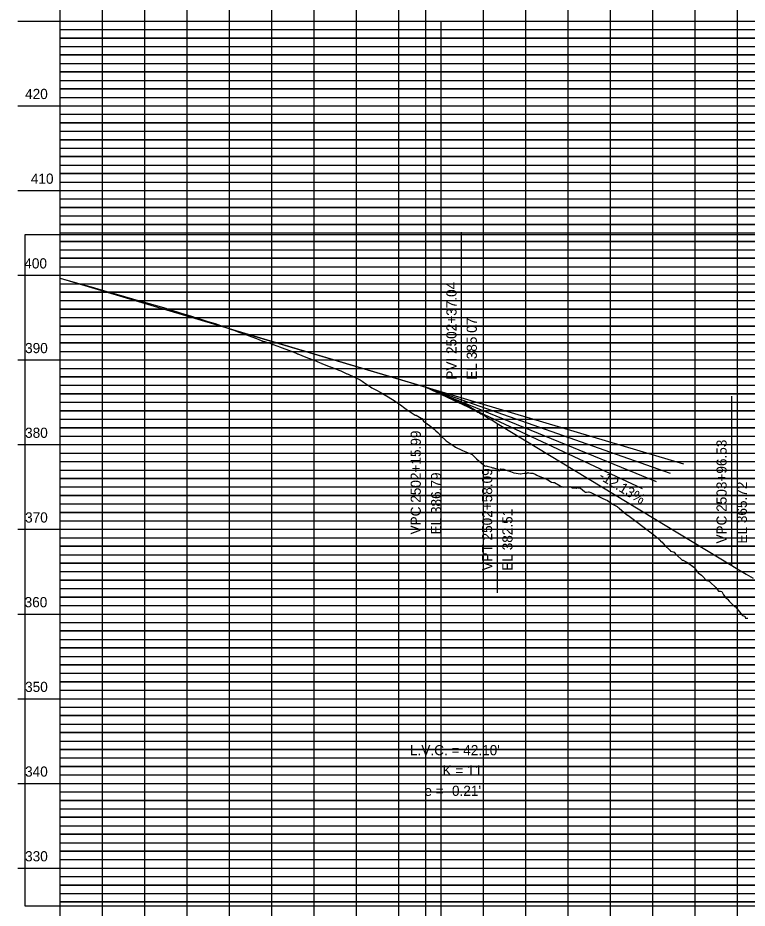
# Model space of a CAD drawing. Extents: x 1195880 to 1289360, y 2059330 to 2086925.
# Drawn here: x 1203089 to 1203520, y 2065041 to 2065566 of the extents above; entities that cross this region are included whole.
import ezdxf

# ---------------------------------------------------------------- set-up
doc = ezdxf.new("R2010")
doc.units = 0
for name, color, linetype in [('Clip', 7, 'Continuous'), ('Default', 7, 'Continuous'), ('Existing Ground PGL', 7, 'Continuous'), ('Grid', 7, 'Continuous'), ('Grid Lables', 7, 'Continuous'), ('Profile', 7, 'Continuous'), ('Profile Annotation', 7, 'Continuous')]:
    doc.layers.add(name, color=color, linetype=linetype)

msp = doc.modelspace()

# ---------------------------------------------------------------- linework, layer by layer
at = {"layer": 'Clip'}
msp.add_lwpolyline([(1203093.54, 2065041.86), (1204075.43, 2065041.86), (1204075.43, 2065438.05), (1203093.54, 2065438.05)], close=True, dxfattribs=at)
at = {"layer": 'Default'}
for p, q in [((1203330.32, 2064864.18), (1203330.32, 2065810.63)), ((1203114.36, 2065412.35), (1203482.5, 2065302.89)), ((1203330.32, 2065348.14), (1203474.61, 2065297.26)), ((1203330.32, 2065348.14), (1203466.24, 2065292.48)), ((1203330.32, 2065348.14), (1203458.02, 2065288.35))]:
    msp.add_line(p, q, dxfattribs=at)
at = {"layer": 'Existing Ground PGL'}
msp.add_lwpolyline([(1203114.36, 2065412.35), (1203116.41, 2065411.85), (1203117.09, 2065411.63), (1203117.63, 2065411.46), (1203126.84, 2065408.88), (1203132.6, 2065407.28), (1203141.94, 2065404.58), (1203147.58, 2065402.96), (1203157.03, 2065400.3), (1203162.56, 2065398.76), (1203166.95, 2065397.47), (1203171.82, 2065396.05), (1203171.82, 2065396.05), (1203176.68, 2065394.63), (1203177.53, 2065394.39), (1203181.55, 2065393.16), (1203183.53, 2065392.56), (1203186.42, 2065391.67), (1203191.29, 2065390.19), (1203192.51, 2065389.82), (1203193.18, 2065389.61), (1203194.15, 2065389.3), (1203196.16, 2065388.66), (1203201.03, 2065387.13), (1203201.59, 2065386.95), (1203205.89, 2065385.58), (1203207.51, 2065385.07), (1203209.09, 2065384.5), (1203210.55, 2065383.98), (1203210.76, 2065383.91), (1203215.63, 2065382.16), (1203215.98, 2065382.04), (1203220.5, 2065380.44), (1203222.19, 2065379.85), (1203222.32, 2065379.8), (1203222.52, 2065379.73), (1203224.3, 2065379.04), (1203225.37, 2065378.62), (1203230.24, 2065376.74), (1203233.1, 2065375.63), (1203233.5, 2065375.48), (1203233.63, 2065375.42), (1203233.7, 2065375.4), (1203233.74, 2065375.38), (1203233.94, 2065375.31), (1203233.95, 2065375.31), (1203233.96, 2065375.3), (1203233.97, 2065375.3), (1203234, 2065375.29), (1203234.05, 2065375.28), (1203234.26, 2065375.22), (1203235.1, 2065374.98), (1203237.57, 2065374.29), (1203239.28, 2065373.64), (1203239.97, 2065373.37), (1203240.18, 2065373.29), (1203244.38, 2065371.71), (1203244.84, 2065371.53), (1203247.65, 2065370.47), (1203249.27, 2065369.85), (1203249.71, 2065369.68), (1203252.67, 2065368.56), (1203253.85, 2065368.07), (1203254.58, 2065367.76), (1203254.58, 2065367.75), (1203254.67, 2065367.72), (1203259.44, 2065365.86), (1203263.23, 2065364.39), (1203264.31, 2065363.95), (1203266.13, 2065363.21), (1203267.94, 2065362.48), (1203268.59, 2065362.27), (1203268.7, 2065362.01), (1203269.18, 2065361.84), (1203273.81, 2065360.18), (1203274.05, 2065360.09), (1203278.92, 2065358.18), (1203280.06, 2065357.73), (1203283.63, 2065356.05), (1203283.79, 2065355.98), (1203284.4, 2065355.73), (1203285.58, 2065355.23), (1203286.52, 2065354.85), (1203288.65, 2065353.79), (1203291.43, 2065352.4), (1203292.62, 2065351.61), (1203293.52, 2065351), (1203297.59, 2065348.2), (1203298.39, 2065347.78), (1203301.07, 2065346.38), (1203303.26, 2065345.13), (1203308.13, 2065342.34), (1203309.68, 2065341.43), (1203311.5, 2065340.19), (1203313, 2065339.2), (1203315.39, 2065337.6), (1203317.86, 2065335.7), (1203318.62, 2065335.12), (1203322.73, 2065332.38), (1203324.05, 2065331.49), (1203324.55, 2065331.5), (1203327.6, 2065329.75), (1203327.83, 2065329.62), (1203328.99, 2065327.95), (1203332.47, 2065325.4), (1203335.21, 2065323.36), (1203336.28, 2065322.24), (1203337.34, 2065321.24), (1203339.23, 2065319.42), (1203341.83, 2065316.75), (1203342.2, 2065316.49), (1203347.08, 2065313.22), (1203347.84, 2065312.71), (1203351.49, 2065310.84), (1203351.96, 2065310.65), (1203356.84, 2065308.7), (1203357.55, 2065308.42), (1203360.16, 2065305.79), (1203361.71, 2065304.49), (1203365.32, 2065301.48), (1203366.16, 2065301.56), (1203366.59, 2065301.45), (1203368.87, 2065300.83), (1203369.6, 2065300.46), (1203370.04, 2065300.52), (1203370.17, 2065300.5), (1203371.47, 2065300.17), (1203372.85, 2065299.81), (1203373.61, 2065298.55), (1203374.54, 2065299.9), (1203376.33, 2065299.6), (1203376.34, 2065299.6), (1203377.66, 2065299.04), (1203380.28, 2065298.22), (1203381.22, 2065297.86), (1203382.15, 2065297.49), (1203383.66, 2065297.4), (1203385.94, 2065296.86), (1203386.1, 2065296.9), (1203388.32, 2065297.4), (1203389.27, 2065297.02), (1203390.46, 2065297.64), (1203390.97, 2065297.53), (1203392.01, 2065297.29), (1203393.44, 2065297.4), (1203394.92, 2065296.7), (1203395.85, 2065296.16), (1203396.63, 2065295.7), (1203400.73, 2065294.26), (1203401.39, 2065294.02), (1203402.36, 2065293.44), (1203404.4, 2065292.09), (1203405.6, 2065291.79), (1203405.8, 2065291.74), (1203406.24, 2065291.76), (1203409.5, 2065289.84), (1203410.2, 2065289.24), (1203410.42, 2065289.56), (1203410.48, 2065289.53), (1203410.91, 2065289.34), (1203411.56, 2065289.13), (1203415.36, 2065289.42), (1203415.38, 2065289.43), (1203416.72, 2065288.76), (1203419.3, 2065288.41), (1203419.8, 2065288.81), (1203420.23, 2065288.73), (1203421.58, 2065288.48), (1203423.93, 2065286.45), (1203424.64, 2065286.12), (1203425.11, 2065286.2), (1203426.26, 2065286.38), (1203426.62, 2065286.37), (1203427.76, 2065285.88), (1203429.99, 2065284.79), (1203434.87, 2065282.39), (1203437.46, 2065281.1), (1203439.74, 2065279.59), (1203440.58, 2065279.02), (1203443.35, 2065277.67), (1203443.64, 2065277.24), (1203444.22, 2065276.77), (1203444.62, 2065276.44), (1203448.6, 2065273.14), (1203449.43, 2065272.55), (1203449.5, 2065272.5), (1203454.37, 2065268.9), (1203459.25, 2065265.24), (1203464.13, 2065261.53), (1203464.25, 2065261.44), (1203464.52, 2065261.23), (1203464.71, 2065261.02), (1203466.21, 2065259.75), (1203468.38, 2065257.7), (1203469, 2065257.07), (1203469.27, 2065256.8), (1203469.59, 2065256.71), (1203471.64, 2065254.5), (1203473.88, 2065252.27), (1203474.31, 2065251.84), (1203474.9, 2065251.17), (1203475.03, 2065251.18), (1203476.98, 2065250.65), (1203477.47, 2065249.86), (1203478.76, 2065248.7), (1203481.3, 2065246.36), (1203481.61, 2065246.06), (1203482.28, 2065245.89), (1203483.63, 2065245.16), (1203484.77, 2065244.54), (1203488.51, 2065241.76), (1203488.68, 2065241.63), (1203491.16, 2065238.55), (1203493.03, 2065237.03), (1203493.39, 2065236.67), (1203496.05, 2065233.98), (1203497.56, 2065233.61), (1203498.26, 2065232.97), (1203501.57, 2065229.92), (1203502.42, 2065228.53), (1203503.13, 2065227.72), (1203503.14, 2065227.72), (1203504.24, 2065227.73), (1203505.1, 2065227.48), (1203506.08, 2065225.47), (1203507.33, 2065223.71), (1203508.02, 2065223.3), (1203508.44, 2065223.04), (1203509.42, 2065221.85), (1203512.52, 2065218.6), (1203512.89, 2065218.54), (1203513.05, 2065218.51), (1203516.19, 2065214.5), (1203516.88, 2065213.63), (1203517.34, 2065213.28), (1203517.77, 2065213.17), (1203518.6, 2065212.94), (1203518.95, 2065211.7), (1203519.52, 2065211.66), (1203520.46, 2065211.74)], dxfattribs=at)
at = {"layer": 'Grid'}
for p, q in [((1203114.36, 2064864.18), (1203114.36, 2065664.18)), ((1203139.36, 2064864.18), (1203139.36, 2065664.18)), ((1203164.36, 2064864.18), (1203164.36, 2065664.18)), ((1203189.36, 2064864.18), (1203189.36, 2065664.18)), ((1203214.36, 2064864.18), (1203214.36, 2065664.18)), ((1203239.36, 2064864.18), (1203239.36, 2065664.18)), ((1203264.36, 2064864.18), (1203264.36, 2065664.18)), ((1203289.36, 2064864.18), (1203289.36, 2065664.18)), ((1203314.36, 2064864.18), (1203314.36, 2065664.18)), ((1203364.36, 2064864.18), (1203364.36, 2065664.18)), ((1203389.36, 2064864.18), (1203389.36, 2065664.18)), ((1203414.36, 2064864.18), (1203414.36, 2065664.18)), ((1203439.36, 2064864.18), (1203439.36, 2065664.18)), ((1203464.36, 2064864.18), (1203464.36, 2065664.18)), ((1203489.36, 2064864.18), (1203489.36, 2065664.18)), ((1203514.36, 2064864.18), (1203514.36, 2065664.18)), ((1203089.36, 2065564.18), (1203114.36, 2065564.18)), ((1203114.36, 2065564.18), (1204114.36, 2065564.18)), ((1203339.36, 2064764.18), (1203339.36, 2065564.18)), ((1203114.36, 2065559.18), (1203117.36, 2065559.18)), ((1203114.36, 2065559.18), (1204114.36, 2065559.18)), ((1203114.36, 2065554.18), (1203117.36, 2065554.18)), ((1203114.36, 2065554.18), (1204114.36, 2065554.18)), ((1204114.36, 2065554.18), (1203114.36, 2065554.18)), ((1203114.36, 2065549.18), (1203117.36, 2065549.18)), ((1203114.36, 2065549.18), (1204114.36, 2065549.18)), ((1203114.36, 2065544.18), (1203117.36, 2065544.18)), ((1203114.36, 2065544.18), (1204114.36, 2065544.18)), ((1204114.36, 2065544.18), (1203114.36, 2065544.18)), ((1203114.36, 2065539.18), (1203117.36, 2065539.18)), ((1203114.36, 2065539.18), (1204114.36, 2065539.18)), ((1203114.36, 2065534.18), (1203117.36, 2065534.18)), ((1203114.36, 2065534.18), (1204114.36, 2065534.18)), ((1204114.36, 2065534.18), (1203114.36, 2065534.18)), ((1203114.36, 2065529.18), (1203117.36, 2065529.18)), ((1203114.36, 2065529.18), (1204114.36, 2065529.18)), ((1203114.36, 2065524.18), (1203117.36, 2065524.18)), ((1203114.36, 2065524.18), (1204114.36, 2065524.18)), ((1204114.36, 2065524.18), (1203114.36, 2065524.18)), ((1203114.36, 2065519.18), (1203117.36, 2065519.18)), ((1203114.36, 2065519.18), (1204114.36, 2065519.18)), ((1203089.36, 2065514.18), (1203114.36, 2065514.18)), ((1203114.36, 2065514.18), (1204114.36, 2065514.18)), ((1203114.36, 2065509.18), (1203117.36, 2065509.18)), ((1203114.36, 2065509.18), (1204114.36, 2065509.18)), ((1203114.36, 2065504.18), (1203117.36, 2065504.18)), ((1203114.36, 2065504.18), (1204114.36, 2065504.18)), ((1204114.36, 2065504.18), (1203114.36, 2065504.18)), ((1203114.36, 2065499.18), (1203117.36, 2065499.18)), ((1203114.36, 2065499.18), (1204114.36, 2065499.18)), ((1203114.36, 2065494.18), (1203117.36, 2065494.18)), ((1203114.36, 2065494.18), (1204114.36, 2065494.18)), ((1204114.36, 2065494.18), (1203114.36, 2065494.18)), ((1203114.36, 2065489.18), (1203117.36, 2065489.18)), ((1203114.36, 2065489.18), (1204114.36, 2065489.18)), ((1203114.36, 2065484.18), (1203117.36, 2065484.18)), ((1203114.36, 2065484.18), (1204114.36, 2065484.18)), ((1204114.36, 2065484.18), (1203114.36, 2065484.18)), ((1203114.36, 2065479.18), (1203117.36, 2065479.18)), ((1203114.36, 2065479.18), (1204114.36, 2065479.18)), ((1203114.36, 2065474.18), (1203117.36, 2065474.18)), ((1203114.36, 2065474.18), (1204114.36, 2065474.18)), ((1204114.36, 2065474.18), (1203114.36, 2065474.18)), ((1203114.36, 2065469.18), (1203117.36, 2065469.18)), ((1203114.36, 2065469.18), (1204114.36, 2065469.18)), ((1203089.36, 2065464.18), (1203114.36, 2065464.18)), ((1203114.36, 2065464.18), (1204114.36, 2065464.18)), ((1203114.36, 2065459.18), (1203117.36, 2065459.18)), ((1203114.36, 2065459.18), (1204114.36, 2065459.18)), ((1203114.36, 2065454.18), (1203117.36, 2065454.18)), ((1203114.36, 2065454.18), (1204114.36, 2065454.18)), ((1204114.36, 2065454.18), (1203114.36, 2065454.18)), ((1203114.36, 2065449.18), (1203117.36, 2065449.18)), ((1203114.36, 2065449.18), (1204114.36, 2065449.18)), ((1203114.36, 2065444.18), (1203117.36, 2065444.18)), ((1203114.36, 2065444.18), (1204114.36, 2065444.18)), ((1204114.36, 2065444.18), (1203114.36, 2065444.18)), ((1203114.36, 2065439.18), (1203117.36, 2065439.18)), ((1203114.36, 2065439.18), (1204114.36, 2065439.18)), ((1203114.36, 2065434.18), (1203117.36, 2065434.18)), ((1203114.36, 2065434.18), (1204114.36, 2065434.18)), ((1204114.36, 2065434.18), (1203114.36, 2065434.18)), ((1203114.36, 2065429.18), (1203117.36, 2065429.18)), ((1203114.36, 2065429.18), (1204114.36, 2065429.18)), ((1203114.36, 2065424.18), (1203117.36, 2065424.18)), ((1203114.36, 2065424.18), (1204114.36, 2065424.18)), ((1204114.36, 2065424.18), (1203114.36, 2065424.18)), ((1203114.36, 2065419.18), (1203117.36, 2065419.18)), ((1203114.36, 2065419.18), (1204114.36, 2065419.18)), ((1203089.36, 2065414.18), (1203114.36, 2065414.18)), ((1203114.36, 2065414.18), (1204114.36, 2065414.18)), ((1203114.36, 2065409.18), (1203117.36, 2065409.18)), ((1203114.36, 2065409.18), (1204114.36, 2065409.18)), ((1203114.36, 2065404.18), (1203117.36, 2065404.18)), ((1203114.36, 2065404.18), (1204114.36, 2065404.18)), ((1204114.36, 2065404.18), (1203114.36, 2065404.18)), ((1203114.36, 2065399.18), (1203117.36, 2065399.18)), ((1203114.36, 2065399.18), (1204114.36, 2065399.18)), ((1203114.36, 2065394.18), (1203117.36, 2065394.18)), ((1203114.36, 2065394.18), (1204114.36, 2065394.18)), ((1204114.36, 2065394.18), (1203114.36, 2065394.18)), ((1203114.36, 2065389.18), (1203117.36, 2065389.18)), ((1203114.36, 2065389.18), (1204114.36, 2065389.18)), ((1203114.36, 2065384.18), (1203117.36, 2065384.18)), ((1203114.36, 2065384.18), (1204114.36, 2065384.18)), ((1204114.36, 2065384.18), (1203114.36, 2065384.18)), ((1203114.36, 2065379.18), (1203117.36, 2065379.18)), ((1203114.36, 2065379.18), (1204114.36, 2065379.18)), ((1203114.36, 2065374.18), (1203117.36, 2065374.18)), ((1203114.36, 2065374.18), (1204114.36, 2065374.18)), ((1204114.36, 2065374.18), (1203114.36, 2065374.18)), ((1203114.36, 2065369.18), (1203117.36, 2065369.18)), ((1203114.36, 2065369.18), (1204114.36, 2065369.18)), ((1203089.36, 2065364.18), (1203114.36, 2065364.18)), ((1203114.36, 2065364.18), (1204114.36, 2065364.18)), ((1203114.36, 2065359.18), (1203117.36, 2065359.18)), ((1203114.36, 2065359.18), (1204114.36, 2065359.18)), ((1203114.36, 2065354.18), (1203117.36, 2065354.18)), ((1203114.36, 2065354.18), (1204114.36, 2065354.18)), ((1204114.36, 2065354.18), (1203114.36, 2065354.18)), ((1203114.36, 2065349.18), (1203117.36, 2065349.18)), ((1203114.36, 2065349.18), (1204114.36, 2065349.18)), ((1203114.36, 2065344.18), (1203117.36, 2065344.18)), ((1203114.36, 2065344.18), (1204114.36, 2065344.18)), ((1204114.36, 2065344.18), (1203114.36, 2065344.18)), ((1203114.36, 2065339.18), (1203117.36, 2065339.18)), ((1203114.36, 2065339.18), (1204114.36, 2065339.18)), ((1203114.36, 2065334.18), (1203117.36, 2065334.18)), ((1203114.36, 2065334.18), (1204114.36, 2065334.18)), ((1204114.36, 2065334.18), (1203114.36, 2065334.18)), ((1203114.36, 2065329.18), (1203117.36, 2065329.18)), ((1203114.36, 2065329.18), (1204114.36, 2065329.18)), ((1203114.36, 2065324.18), (1203117.36, 2065324.18)), ((1203114.36, 2065324.18), (1204114.36, 2065324.18)), ((1204114.36, 2065324.18), (1203114.36, 2065324.18)), ((1203114.36, 2065319.18), (1203117.36, 2065319.18)), ((1203114.36, 2065319.18), (1204114.36, 2065319.18)), ((1203089.36, 2065314.18), (1203114.36, 2065314.18)), ((1203114.36, 2065314.18), (1204114.36, 2065314.18)), ((1203114.36, 2065309.18), (1203117.36, 2065309.18)), ((1203114.36, 2065309.18), (1204114.36, 2065309.18)), ((1203114.36, 2065304.18), (1203117.36, 2065304.18)), ((1203114.36, 2065304.18), (1204114.36, 2065304.18)), ((1203114.36, 2065299.18), (1203117.36, 2065299.18)), ((1203114.36, 2065299.18), (1204114.36, 2065299.18)), ((1203114.36, 2065294.18), (1203117.36, 2065294.18)), ((1203114.36, 2065294.18), (1204114.36, 2065294.18)), ((1204114.36, 2065294.18), (1203114.36, 2065294.18)), ((1203114.36, 2065289.18), (1203117.36, 2065289.18)), ((1203114.36, 2065289.18), (1204114.36, 2065289.18)), ((1203114.36, 2065284.18), (1203117.36, 2065284.18)), ((1203114.36, 2065284.18), (1204114.36, 2065284.18)), ((1204114.36, 2065284.18), (1203114.36, 2065284.18)), ((1203114.36, 2065279.18), (1203117.36, 2065279.18)), ((1203114.36, 2065279.18), (1204114.36, 2065279.18)), ((1203114.36, 2065274.18), (1203117.36, 2065274.18)), ((1203114.36, 2065274.18), (1204114.36, 2065274.18)), ((1204114.36, 2065274.18), (1203114.36, 2065274.18)), ((1203114.36, 2065269.18), (1203117.36, 2065269.18)), ((1203114.36, 2065269.18), (1204114.36, 2065269.18)), ((1203089.36, 2065264.18), (1203114.36, 2065264.18)), ((1203114.36, 2065264.18), (1204114.36, 2065264.18)), ((1203114.36, 2065259.18), (1203117.36, 2065259.18)), ((1203114.36, 2065259.18), (1204114.36, 2065259.18)), ((1203114.36, 2065254.18), (1203117.36, 2065254.18)), ((1203114.36, 2065254.18), (1204114.36, 2065254.18)), ((1204114.36, 2065254.18), (1203114.36, 2065254.18)), ((1203114.36, 2065249.18), (1203117.36, 2065249.18)), ((1203114.36, 2065249.18), (1204114.36, 2065249.18)), ((1203114.36, 2065244.18), (1203117.36, 2065244.18)), ((1203114.36, 2065244.18), (1204114.36, 2065244.18)), ((1204114.36, 2065244.18), (1203114.36, 2065244.18)), ((1203114.36, 2065239.18), (1203117.36, 2065239.18)), ((1203114.36, 2065239.18), (1204114.36, 2065239.18)), ((1203114.36, 2065234.18), (1203117.36, 2065234.18)), ((1203114.36, 2065234.18), (1204114.36, 2065234.18)), ((1204114.36, 2065234.18), (1203114.36, 2065234.18)), ((1203114.36, 2065229.18), (1203117.36, 2065229.18)), ((1203114.36, 2065229.18), (1204114.36, 2065229.18)), ((1203114.36, 2065224.18), (1203117.36, 2065224.18)), ((1203114.36, 2065224.18), (1204114.36, 2065224.18)), ((1204114.36, 2065224.18), (1203114.36, 2065224.18)), ((1203114.36, 2065219.18), (1203117.36, 2065219.18)), ((1203114.36, 2065219.18), (1204114.36, 2065219.18)), ((1203089.36, 2065214.18), (1203114.36, 2065214.18)), ((1203114.36, 2065214.18), (1204114.36, 2065214.18)), ((1203114.36, 2065209.18), (1203117.36, 2065209.18)), ((1203114.36, 2065209.18), (1204114.36, 2065209.18)), ((1203114.36, 2065204.18), (1203117.36, 2065204.18)), ((1203114.36, 2065204.18), (1204114.36, 2065204.18)), ((1204114.36, 2065204.18), (1203114.36, 2065204.18)), ((1203114.36, 2065199.18), (1203117.36, 2065199.18)), ((1203114.36, 2065199.18), (1204114.36, 2065199.18)), ((1203114.36, 2065194.18), (1203117.36, 2065194.18)), ((1203114.36, 2065194.18), (1204114.36, 2065194.18)), ((1204114.36, 2065194.18), (1203114.36, 2065194.18)), ((1203114.36, 2065189.18), (1203117.36, 2065189.18)), ((1203114.36, 2065189.18), (1204114.36, 2065189.18)), ((1203114.36, 2065184.18), (1203117.36, 2065184.18)), ((1203114.36, 2065184.18), (1204114.36, 2065184.18)), ((1204114.36, 2065184.18), (1203114.36, 2065184.18)), ((1203114.36, 2065179.18), (1203117.36, 2065179.18)), ((1203114.36, 2065179.18), (1204114.36, 2065179.18)), ((1203114.36, 2065174.18), (1203117.36, 2065174.18)), ((1203114.36, 2065174.18), (1204114.36, 2065174.18)), ((1204114.36, 2065174.18), (1203114.36, 2065174.18)), ((1203114.36, 2065169.18), (1203117.36, 2065169.18)), ((1203114.36, 2065169.18), (1204114.36, 2065169.18)), ((1203089.36, 2065164.18), (1203114.36, 2065164.18)), ((1203114.36, 2065164.18), (1204114.36, 2065164.18)), ((1203114.36, 2065159.18), (1203117.36, 2065159.18)), ((1203114.36, 2065159.18), (1204114.36, 2065159.18)), ((1203114.36, 2065154.18), (1203117.36, 2065154.18)), ((1203114.36, 2065154.18), (1204114.36, 2065154.18)), ((1204114.36, 2065154.18), (1203114.36, 2065154.18)), ((1203114.36, 2065149.18), (1203117.36, 2065149.18)), ((1203114.36, 2065149.18), (1204114.36, 2065149.18)), ((1203114.36, 2065144.18), (1203117.36, 2065144.18)), ((1203114.36, 2065144.18), (1204114.36, 2065144.18)), ((1204114.36, 2065144.18), (1203114.36, 2065144.18)), ((1203114.36, 2065139.18), (1203117.36, 2065139.18)), ((1203114.36, 2065139.18), (1204114.36, 2065139.18)), ((1203114.36, 2065134.18), (1203117.36, 2065134.18)), ((1203114.36, 2065134.18), (1204114.36, 2065134.18)), ((1204114.36, 2065134.18), (1203114.36, 2065134.18)), ((1203114.36, 2065129.18), (1203117.36, 2065129.18)), ((1203114.36, 2065129.18), (1204114.36, 2065129.18)), ((1203114.36, 2065124.18), (1203117.36, 2065124.18)), ((1203114.36, 2065124.18), (1204114.36, 2065124.18)), ((1204114.36, 2065124.18), (1203114.36, 2065124.18)), ((1203114.36, 2065119.18), (1203117.36, 2065119.18)), ((1203114.36, 2065119.18), (1204114.36, 2065119.18)), ((1203089.36, 2065114.18), (1203114.36, 2065114.18)), ((1203114.36, 2065114.18), (1204114.36, 2065114.18)), ((1203114.36, 2065109.18), (1203117.36, 2065109.18)), ((1203114.36, 2065109.18), (1204114.36, 2065109.18)), ((1203114.36, 2065104.18), (1203117.36, 2065104.18)), ((1203114.36, 2065104.18), (1204114.36, 2065104.18)), ((1204114.36, 2065104.18), (1203114.36, 2065104.18)), ((1203114.36, 2065099.18), (1203117.36, 2065099.18)), ((1203114.36, 2065099.18), (1204114.36, 2065099.18)), ((1203114.36, 2065094.18), (1203117.36, 2065094.18)), ((1203114.36, 2065094.18), (1204114.36, 2065094.18)), ((1204114.36, 2065094.18), (1203114.36, 2065094.18)), ((1203114.36, 2065089.18), (1203117.36, 2065089.18)), ((1203114.36, 2065089.18), (1204114.36, 2065089.18)), ((1203114.36, 2065084.18), (1203117.36, 2065084.18)), ((1203114.36, 2065084.18), (1204114.36, 2065084.18)), ((1204114.36, 2065084.18), (1203114.36, 2065084.18)), ((1203114.36, 2065079.18), (1203117.36, 2065079.18)), ((1203114.36, 2065079.18), (1204114.36, 2065079.18)), ((1203114.36, 2065074.18), (1203117.36, 2065074.18)), ((1203114.36, 2065074.18), (1204114.36, 2065074.18)), ((1204114.36, 2065074.18), (1203114.36, 2065074.18)), ((1203114.36, 2065069.18), (1203117.36, 2065069.18)), ((1203114.36, 2065069.18), (1204114.36, 2065069.18)), ((1203089.36, 2065064.18), (1203114.36, 2065064.18)), ((1203114.36, 2065064.18), (1204114.36, 2065064.18)), ((1203114.36, 2065059.18), (1203117.36, 2065059.18)), ((1203114.36, 2065059.18), (1204114.36, 2065059.18)), ((1203114.36, 2065054.18), (1203117.36, 2065054.18)), ((1203114.36, 2065054.18), (1204114.36, 2065054.18)), ((1204114.36, 2065054.18), (1203114.36, 2065054.18)), ((1203114.36, 2065049.18), (1203117.36, 2065049.18)), ((1203114.36, 2065049.18), (1204114.36, 2065049.18)), ((1203114.36, 2065044.18), (1203117.36, 2065044.18)), ((1203114.36, 2065044.18), (1204114.36, 2065044.18)), ((1204114.36, 2065044.18), (1203114.36, 2065044.18))]:
    msp.add_line(p, q, dxfattribs=at)
at = {"layer": 'Profile'}
for p, q in [((1203214.37, 2065382.61), (1203330.35, 2065348.13)), ((1203330.35, 2065348.13), (1203330.35, 2065348.13)), ((1203372.46, 2065326.74), (1203510.89, 2065242.77))]:
    msp.add_line(p, q, dxfattribs=at)
for points in [[(1203330.35, 2065348.13), (1203331.23, 2065347.77), (1203332.11, 2065347.4), (1203332.98, 2065347.03), (1203333.86, 2065346.66), (1203334.74, 2065346.29), (1203335.62, 2065345.91), (1203336.49, 2065345.53), (1203337.37, 2065345.14), (1203338.25, 2065344.75), (1203339.12, 2065344.36), (1203340, 2065343.96), (1203340.88, 2065343.56), (1203341.76, 2065343.15), (1203342.63, 2065342.75), (1203343.51, 2065342.33), (1203344.39, 2065341.92), (1203345.26, 2065341.5), (1203346.14, 2065341.08), (1203347.02, 2065340.65), (1203347.9, 2065340.22), (1203348.77, 2065339.79), (1203349.65, 2065339.35), (1203350.53, 2065338.91), (1203352.28, 2065338.02), (1203353.16, 2065337.57), (1203354.04, 2065337.12), (1203354.91, 2065336.66), (1203355.79, 2065336.2), (1203356.67, 2065335.73), (1203357.54, 2065335.26), (1203358.42, 2065334.79), (1203359.3, 2065334.31), (1203360.18, 2065333.83), (1203361.05, 2065333.35), (1203361.93, 2065332.86), (1203362.81, 2065332.37), (1203363.68, 2065331.88), (1203364.56, 2065331.38), (1203365.44, 2065330.88), (1203366.32, 2065330.37), (1203367.19, 2065329.87), (1203368.07, 2065329.35), (1203368.95, 2065328.84), (1203369.82, 2065328.32), (1203370.7, 2065327.8), (1203371.58, 2065327.27), (1203372.46, 2065326.74)], [(1203510.89, 2065242.77), (1203515.11, 2065240.23), (1203519.34, 2065237.72), (1203523.56, 2065235.25)]]:
    msp.add_lwpolyline(points, dxfattribs=at)
at = {"layer": 'Profile Annotation'}
for p, q in [((1203351.4, 2065339.51), (1203351.4, 2065439.51)), ((1203330.32, 2065248.14), (1203330.32, 2065348.14)), ((1203340.88, 2065343.82), (1203351.4, 2065339.51)), ((1203510.89, 2065242.77), (1203510.89, 2065342.77)), ((1203351.4, 2065339.51), (1203361.93, 2065333.12)), ((1203372.46, 2065326.74), (1203372.46, 2065226.74))]:
    msp.add_line(p, q, dxfattribs=at)

# ---------------------------------------------------------------- texts
at = {"layer": 'Grid Lables'}
for s, p in [('420', (1203093.67, 2065518.18)), ('410', (1203097.07, 2065468.18)), ('400', (1203093.2, 2065418.18)), ('390', (1203093.67, 2065368.18)), ('380', (1203093.67, 2065318.18)), ('370', (1203093.67, 2065268.18)), ('360', (1203093.39, 2065218.18)), ('350', (1203093.67, 2065168.18)), ('340', (1203093.67, 2065118.18)), ('330', (1203093.67, 2065068.18))]:
    msp.add_text(s, height=6, dxfattribs=at).set_placement(p)
at = {"layer": 'Profile Annotation'}
for s, rotation, p in [('PVI 2502+37.04', 90, (1203348.4, 2065352.51)), ('EL 385.07', 90, (1203360.4, 2065352.51)), ('VPC 2502+15.99', 90, (1203327.32, 2065261.14)), ('VPC 2503+96.53', 90, (1203507.89, 2065255.77)), ('VPT 2502+58.09', 90, (1203369.46, 2065239.74)), ('EL 386.79', 90, (1203339.32, 2065261.14)), ('-12.13%', 328.7618, (1203431.9, 2065294.19)), ('EL 365.72', 90, (1203519.89, 2065255.77)), ('EL 382.51', 90, (1203381.46, 2065239.74))]:
    msp.add_text(s, height=6, rotation=rotation, dxfattribs=at).set_placement(p)
for s, p in [("L.V.C. = 42.10'", (1203320.93, 2065130.81)), ('K = 11', (1203340.11, 2065118.81)), ("e = -0.21'", (1203329.44, 2065106.81))]:
    msp.add_text(s, height=6, dxfattribs=at).set_placement(p)

doc.saveas('drawing.dxf')
